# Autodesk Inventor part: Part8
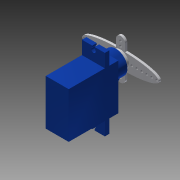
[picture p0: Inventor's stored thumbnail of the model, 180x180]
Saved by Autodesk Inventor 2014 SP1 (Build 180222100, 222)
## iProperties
Created: 2017-05
Part Number: Part8
Material: Generic
Document SubType Name: Modeling
Designer: L.Đ.P
Density: 1 g/cm^3
Appearance: Default
Author: L.Đ.P
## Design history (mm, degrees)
sketch "Sketch1"
  geometry: L1 (5.075, -10.1)-(-5.075, -10.1); L2 (-5.075, -10.1)-(-5.075, 10.1); L3 (-5.075, 10.1)-(5.075, 10.1); L4 (5.075, 10.1)-(5.075, -10.1); L5 (0, 0)-(0, -6.792); L6 (0, 0)-(-3.426, 0); 2 further points
  constraints: 12 end point, 3 parallel, 2 midpoint, 2 perpendicular, 2 point on line, 1 horizontal
  dimensions: "d0" = 10.15 distance of L2.end L3.end; "d1" = 20.2 distance of L1.end L2.end
extrude "Extrusion1" new body sketch "Sketch1" distance "d2" = 16; taper "d3" = 0 deg
sketch "Sketch2"
  geometry: L1 (5.075, 10.1)-(-5.075, 10.1) reference; L2 (-5.075, 10.1)-(-5.075, -10.1) reference; L3 (5.075, -10.1)-(5.075, 10.1) reference; L4 (5.075, -16)-(-5.075, -16); L5 (-5.075, -16)-(-5.075, 16); L6 (-5.075, 16)-(5.075, 16); L7 (5.075, 16)-(5.075, -16); 3 further points
  constraints: 8 end point, 4 midpoint, 2 parallel, 1 horizontal, 1 perpendicular
  dimensions: "d4" = 32 distance between parallel lines of L4 L6
extrude "Extrusion2" join sketch "Sketch2" distance "d5" = 2; taper "d6" = 0 deg
sketch "Sketch3"
  geometry: L1 (5.075, -16)-(-5.075, -16) reference; L2 (-5.075, -16)-(-5.075, 16) reference; L3 (-5.075, 16)-(5.075, 16) reference; L4 (5.075, 16)-(5.075, -16) reference; L5 (5.075, -16)-(-5.075, -16) reference; L6 (-5.075, -16)-(-5.075, 16) reference; L7 (-5.075, 16)-(5.075, 16) reference; L8 (5.075, 16)-(5.075, -16) reference; L9 (-5.075, 10.1)-(5.075, 10.1) reference; L10 (5.075, 10.1)-(5.075, -10.1) reference; L11 (5.075, -10.1)-(-5.075, -10.1) reference; L12 (-5.075, -10.1)-(-5.075, 10.1) reference; 1 further point
extrude "Extrusion3" join sketch "Sketch3" distance "d7" = 4; taper "d8" = 0 deg
sketch "Sketch4"
  geometry: L1 (-5.075, 10.1)-(-5.075, -10.1) reference; L2 (-5.075, -10.1)-(5.075, -10.1) reference; L3 (5.075, -10.1)-(5.075, 10.1) reference; C1 r 5.075 at (0, -5.025); C2 r 1.5 at (0, 0.675); 1 further point
  constraints: 3 tangent, 2 centre point
  dimensions: "d10" = 3 diameter of C2; "d11" = 5.7 distance of C1.centre C2.centre; "d12" = 5.075 distance from line of L3 C2.centre
extrude "Extrusion4" join sketch "Sketch4" distance "d13" = 4; taper "d14" = 0 deg
sketch "Sketch5"
  geometry: L1 (-5.075, -16)-(5.075, -16) reference; L2 (5.075, -16)-(5.075, -10.1) reference; L3 (0.5, -16)-(-0.5, -16); L4 (-0.5, -16)-(-0.5, -15); L5 (-0.5, -15)-(0.5, -15); L6 (0.5, -15)-(0.5, -16); C1 r 1 at (0, -14.5); 2 further points
  constraints: 8 end point, 2 midpoint, 2 parallel, 1 centre point, 1 horizontal, 1 perpendicular, 1 point on line
  dimensions: "d15" = 2 diameter of C1; "d16" = 1.5 distance from line of L1 C1.centre; "d17" = 1 distance of L4.end L5.end; "d18" = 1 distance of L3.end L4.end; "d19" = 5.075 distance from line of L2 C1.centre
extrude "Extrusion5" cut sketch "Sketch5" distance "d20" = 4; taper "d21" = 0 deg
sketch "Sketch6"
  geometry: C1 r 3.75 at (0, -5.025); A1 r 5.075 centre (0, -5.025) between (-1.276, -0.113) and (1.276, -0.113) reference; 1 further point
  constraints: 1 centre point, 1 coincident
  dimensions: "d22" = 7.5 diameter of C1
extrude "Extrusion6" join sketch "Sketch6" distance "d23" = 2; taper "d24" = 0 deg
sketch "Sketch7" dims "d25" = 17
  geometry: L1 (2, -7)-(-2, -7); L2 (-2, -7)-(-2, 7); L3 (-2, 7)-(2, 7); L4 (2, 7)-(2, -7); L5 (0, 0)-(0, 1.755); L6 (0, 0)-(1.491, 0); C1 r 3.75 at (0, 0) reference; 5 further points; 1 other entity
  constraints: 12 end point, 3 midpoint, 3 parallel, 2 coincident, 2 horizontal alignment, 2 perpendicular, 2 point on line, 1 horizontal, 7 other
  dimensions: "d26" = 14 distance of L1.end L2.end; "d27" = 4 distance of L2.end L3.end
extrude "Extrusion7" join sketch "Sketch7" distance "d28" = 1; taper "d29" = 0 deg
sketch "Sketch8"
  geometry: C1 r 2 at (0, 0); 4 further points; 1 other entity
  constraints: 1 centre point, 1 coincident, 1 other
  dimensions: "d30" = 4 diameter of C1
extrude "Extrusion8" cut sketch "Sketch8" distance "d31" = 1; taper "d32" = 0 deg
sketch "Sketch9"
  geometry: L1 (0, 0)-(5.408, 0); C1 r 0.5 at (0, 7); C2 r 0.5 at (0, 5.025); C3 r 0.5 at (0, -7); C4 r 0.5 at (0, -5.025); A1 r 2 centre (0, 7) between (2, 7) and (-2, 7) reference; 5 further points; 1 other entity
  constraints: 4 centre point, 4 coincident, 4 symmetric about line, 2 end point, 1 horizontal, 3 other
  dimensions: "d33" = 1 diameter of C1; "d34" = 1 diameter of C2
extrude "Extrusion9" cut sketch "Sketch9" distance "d35" = 1; taper "d36" = 0 deg
sketch "Sketch10" dims "d46" = 10
  geometry: L1 (0, 0)-(-1.343, 0); L2 (-2, 7)-(-2, 3.724) reference; L3 (0, 0)-(0, 1.201); C1 r 0.5 at (-16, 0); C2 r 0.5 at (-13.8, 0); C3 r 0.5 at (-11.6, 0); C4 r 0.5 at (-9.4, 0); C5 r 0.5 at (-7.2, 0); C6 r 0.5 at (-5, 0); C7 r 0.5 at (5, 0); C8 r 0.5 at (7.2, 0); C9 r 0.5 at (9.4, 0); C10 r 0.5 at (11.6, 0); C11 r 0.5 at (13.8, 0); C12 r 0.5 at (16, 0); 3 further points; 2 other entities
  constraints: 12 centre point, 6 symmetric about line, 4 end point, 2 horizontal, 1 parallel, 1 point on line, 18 other
  dimensions: "d37" = 1 diameter of C1; "d38" = 16 distance of L1.start C1.centre; "d43" = 2.2 distance of C1.centre C2.centre
extrude "Extrusion10" cut sketch "Sketch10" distance "d39" = 1; taper "d40" = 0 deg
mirror "Mirror3"
body "Solid1"
node "Projected Loop1"
node "Project Cut Edges1"
node "Project Cut Edges2"
